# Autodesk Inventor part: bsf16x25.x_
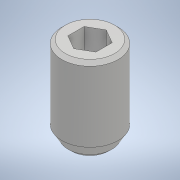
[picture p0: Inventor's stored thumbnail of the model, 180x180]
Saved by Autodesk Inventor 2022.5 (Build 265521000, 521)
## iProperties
Created: 2020-01
Part Number: bsf16x25.x_
Material: 一般
Document SubType Name: Modeling
Designer: ImaoCorp
Density: 1 g/cm^3
Appearance: 既定
Sending System: SOLIDWORKS 2018-2018316
MC: AMD64
MC_MODEL: Intel64 Family 6 Model 60 Stepping 3, GenuineIntel
OS: Windows_NT
FRU: Parasolid Version 30.0, build 310,  6- 8-2018
FORMAT: text
GUISE: transmit
KEY: bsf16x25
FILE: bsf16x25.x_t
DATE: Thu Jan 23 16:49:06 2020
Author: ImaoCorp
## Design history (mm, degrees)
feature "Base1"
node "ソリッド1"
